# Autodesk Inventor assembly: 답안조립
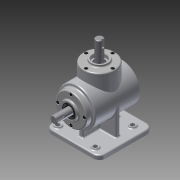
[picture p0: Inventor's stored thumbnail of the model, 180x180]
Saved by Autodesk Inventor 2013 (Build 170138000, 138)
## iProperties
Created: 2015-07
Part Number: 답안조립
Document SubType Name: Assembly
Designer: Administrator
Author: Administrator
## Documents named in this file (14)
- C:\Users\Administrator\Desktop\450706V1006\답안조립.iam
- C:\Users\Administrator\Desktop\450706V1006\본체.ipt
- C:\Users\Administrator\Desktop\450706V1006\메인 축.ipt
- 메인 축.ipt
- C:\Users\Administrator\Desktop\450706V1006\베어링 6203.ipt
- C:\Users\Administrator\Desktop\450706V1006\커버.ipt
- C:\Users\Administrator\Desktop\450706V1006\오일실.ipt
- C:\Users\Administrator\Desktop\450706V1006\M4.ipt
- C:\Users\Administrator\Desktop\450706V1006\메인 베벨기어.ipt
- C:\Users\Administrator\Desktop\450706V1006\키 4x4.ipt
- C:\Users\Administrator\Desktop\450706V1006\서브 베벨기어.ipt
- C:\Users\Administrator\Desktop\450706V1006\서브 축.ipt
- 서브 축.ipt
- C:\Users\Administrator\Desktop\450706V1006\키 5x5.ipt
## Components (8 placed, 1 different names)
1. M4:1
2. M4:2
3. M4:3
4. M4:4
5. M4:5
6. M4:6
7. M4:7
8. M4:8
